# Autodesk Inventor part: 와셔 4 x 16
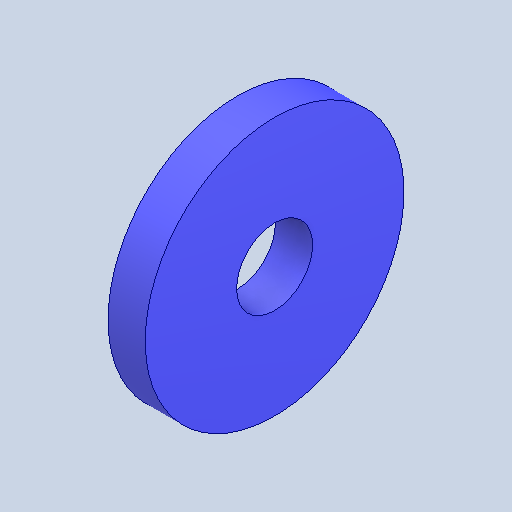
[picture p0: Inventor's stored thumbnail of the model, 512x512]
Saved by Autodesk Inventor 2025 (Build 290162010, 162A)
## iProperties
Created: 2024-07
Part Number: 와셔 4 x 16
Material: 강철, 연강
Description: 미터법 평면 와셔
Document SubType Name: Modeling
Designer: 학생
Density: 7.85 g/cm^3
Appearance: 기본값
Author: jhkim
Sending System: Autodesk Inventor 2025
Preprocessor: ST-DEVELOPER v20
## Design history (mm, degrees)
feature "Solid1"
node "솔리드1"
